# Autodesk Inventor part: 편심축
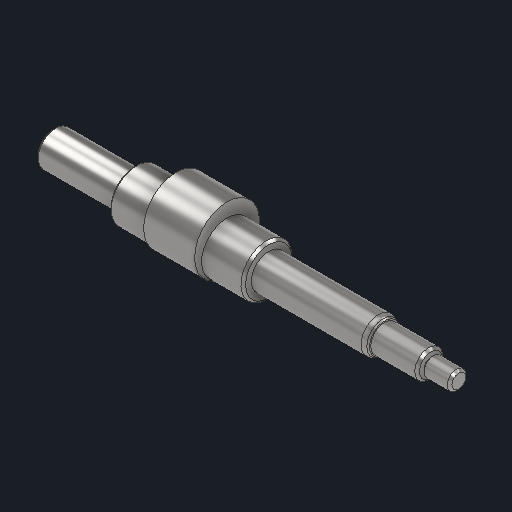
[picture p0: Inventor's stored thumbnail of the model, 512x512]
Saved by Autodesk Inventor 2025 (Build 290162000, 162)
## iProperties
Created: 2025-08
Part Number: 편심축
Material: 강철, 연강
Document SubType Name: Modeling
Designer: infra027
Density: 7.86 g/cm^3
Appearance: 기본값
Author: jhkim
Sending System: Autodesk Inventor 2026
Preprocessor: ST-DEVELOPER v20.1
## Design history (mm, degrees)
feature "솔리드1"
node "솔리드2"
